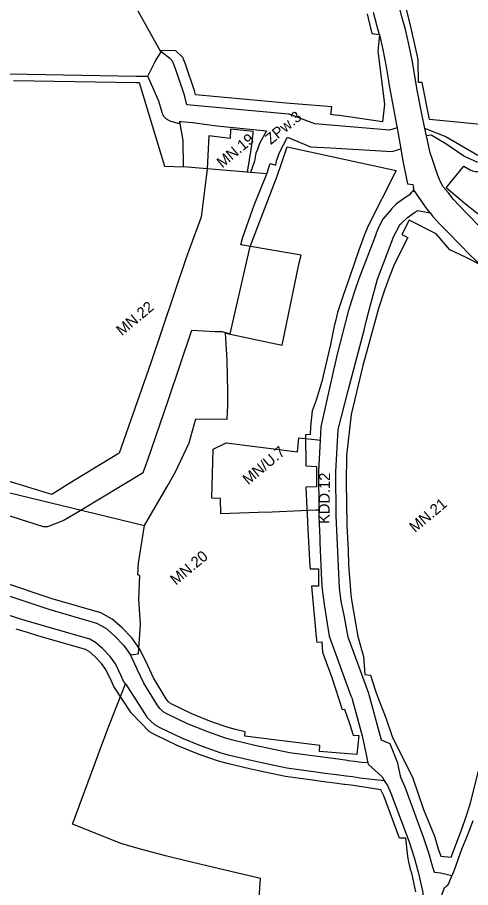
# Model space of a CAD drawing. Extents: x 7418616 to 7420822, y 5550745 to 5553106.
# Drawn here: x 7419932.5 to 7420139.9, y 5552057.3 to 5552455 of the extents above; entities that cross this region are included whole.
import ezdxf

# ---------------------------------------------------------------- set-up
doc = ezdxf.new("R2010")
doc.units = 0
for name, color, linetype in [('linie rozgraniczające', 7, 'Continuous'), ('nieprzekraczalne linie zabudowy', 7, 'Continuous'), ('przeznaczenia terenów', 7, 'Continuous')]:
    doc.layers.add(name, color=color, linetype=linetype)

msp = doc.modelspace()

# ---------------------------------------------------------------- linework, layer by layer
at = {"layer": 'linie rozgraniczające'}
for p, q in [((7420119.69, 5552400.93), (7420118.98, 5552404.25)), ((7420046.7, 5552383.5), (7420039.22, 5552384.12)), ((7420089.21, 5552107.47), (7420100.37, 5552106.25))]:
    msp.add_line(p, q, dxfattribs=at)
for points in [[(7420118.98, 5552404.25), (7420117.7, 5552410.14), (7420115.46, 5552421.78), (7420113.25, 5552434.63), (7420111.63, 5552442.83), (7420110.06, 5552449.46), (7420108.57, 5552454.77), (7420107, 5552460.77)], [(7419998.25, 5552439.19), (7419998.18, 5552439.22), (7419987.78, 5552457.79)], [(7420095.28, 5552457.36), (7420096.79, 5552451.59), (7420098.01, 5552447.24), (7420098.21, 5552447.22), (7420098.16, 5552446.72), (7420098.26, 5552446.35), (7420099.69, 5552440.34), (7420101.24, 5552432.48), (7420102.35, 5552426), (7420102.52, 5552424.72), (7420105.97, 5552405.94), (7420106.22, 5552404.51)], [(7419992.14, 5552428.07), (7419994.56, 5552433.03), (7419995.62, 5552434.82), (7419998.25, 5552439.19)], [(7420106.22, 5552404.51), (7420102.73, 5552403.52), (7420068.67, 5552406.29), (7420056.91, 5552410.74), (7420056.57, 5552410.75), (7420010.03, 5552414.99), (7420009.23, 5552418.27), (7420008.74, 5552419.94), (7420004.72, 5552431.96), (7420003.97, 5552433.91), (7420003.81, 5552434.26), (7420003.62, 5552434.61), (7420003.41, 5552434.94), (7420003.18, 5552435.26), (7420002.94, 5552435.57), (7420002.67, 5552435.85), (7420002.38, 5552436.12), (7420002.08, 5552436.37), (7419998.85, 5552438.79), (7419998.25, 5552439.19)], [(7419926.65, 5552425.28), (7419926.99, 5552429.22), (7419928.76, 5552429.22), (7419986.92, 5552428.2), (7419992.14, 5552428.07)], [(7420006.98, 5552406.44), (7420006.54, 5552406.49), (7420006.04, 5552406.57), (7420005.55, 5552406.69), (7420002.79, 5552407.48), (7420002.16, 5552407.71), (7420001.8, 5552407.87), (7420001.46, 5552408.05), (7420001.12, 5552408.26), (7420000.8, 5552408.49), (7420000.5, 5552408.74), (7420000.21, 5552409.01), (7419999.95, 5552409.29), (7419999.7, 5552409.6), (7419999.47, 5552409.92), (7419999.26, 5552410.25), (7419999.08, 5552410.59), (7419998.91, 5552410.95), (7419998.7, 5552411.55), (7419997.18, 5552416.69), (7419992.14, 5552428.07)], [(7420206.48, 5552414.76), (7420199.14, 5552413.85), (7420162.83, 5552411.03), (7420156.8, 5552405.92), (7420155, 5552397.26), (7420151.77, 5552395.04), (7420146.63, 5552392.74), (7420143.18, 5552391.94), (7420128.29, 5552400.63), (7420118.98, 5552404.25)], [(7420006.98, 5552406.44), (7420006.79, 5552407.54), (7420007.34, 5552407.49), (7420012.61, 5552406.89), (7420020.44, 5552405.83), (7420023.71, 5552405.43), (7420046.41, 5552403.21), (7420043.29, 5552397.35), (7420042.32, 5552394.67), (7420041.6, 5552393), (7420040.96, 5552389.28), (7420039.22, 5552384.12)], [(7420203.99, 5552403.43), (7420199.57, 5552403.26), (7420163.24, 5552408.03), (7420161, 5552407.23), (7420159.6, 5552405.3), (7420157.09, 5552395.64), (7420153.95, 5552392.56), (7420143.19, 5552388.69), (7420136.72, 5552391.55), (7420128.56, 5552397.25), (7420121.84, 5552401.24), (7420119.69, 5552400.93)], [(7420039.22, 5552384.12), (7420008.47, 5552386.68), (7420008.32, 5552398.66), (7420006.98, 5552406.44)], [(7420106.22, 5552404.51), (7420106.69, 5552401.85), (7420107.92, 5552394.9)], [(7420046.7, 5552383.5), (7420048.22, 5552388.16), (7420050.79, 5552387.4), (7420051.1, 5552389.49), (7420052.46, 5552393.32), (7420056.16, 5552400.2), (7420066.62, 5552395.82), (7420075.76, 5552395.35), (7420104, 5552393.77), (7420107.92, 5552394.9)], [(7420147.87, 5552355.44), (7420143.56, 5552359.75), (7420138.73, 5552364.79), (7420134.72, 5552368.9), (7420132.01, 5552371.82), (7420129.55, 5552375.01), (7420127.33, 5552377.61), (7420125.99, 5552380.21), (7420124.9, 5552382.74), (7420123.7, 5552386.34), (7420122.54, 5552389.63), (7420121.39, 5552393.15), (7420119.69, 5552400.93)], [(7420107.92, 5552394.9), (7420108.74, 5552390.22), (7420110.94, 5552378.87), (7420113.43, 5552378.58), (7420113.65, 5552378.01), (7420113.73, 5552376.3)], [(7419990.73, 5552222.78), (7420001.42, 5552241.32), (7420004.84, 5552247.25), (7420011.13, 5552260.48), (7420014.16, 5552271.55), (7420028.46, 5552271.37), (7420028.85, 5552277.74), (7420028.74, 5552284.08), (7420028.48, 5552298.27), (7420027.99, 5552305.76), (7420027.66, 5552310.69), (7420053.64, 5552305.2), (7420061.5, 5552342.83), (7420062.36, 5552346.38), (7420034.68, 5552351), (7420035.59, 5552354.53), (7420040.07, 5552367.09), (7420040.9, 5552369.19), (7420046.7, 5552383.5)], [(7420113.73, 5552376.3), (7420113.36, 5552375.85), (7420113.52, 5552375.4), (7420112.82, 5552375.18), (7420112.18, 5552374.39), (7420112.15, 5552374), (7420109.74, 5552372.46), (7420105.87, 5552369.67), (7420105.67, 5552369.49), (7420103.8, 5552367.62), (7420103.46, 5552367.24), (7420099.78, 5552362.73), (7420097.64, 5552358.67), (7420096.91, 5552356.99), (7420096.69, 5552356.45), (7420096.32, 5552355.38), (7420089.45, 5552337.45), (7420088.75, 5552335.53), (7420086.8, 5552329.69), (7420085.33, 5552325.44), (7420083.82, 5552320.51), (7420078.88, 5552301.03), (7420077.55, 5552295.66), (7420077.45, 5552295.06), (7420071.34, 5552267.92), (7420071.01, 5552261.83)], [(7420121.34, 5552365.68), (7420120.17, 5552367.21), (7420119.7, 5552367.75), (7420118.92, 5552368.85), (7420113.73, 5552376.3)], [(7420131.31, 5552062.66), (7420126.09, 5552063.86), (7420123.32, 5552064.18), (7420122.15, 5552068.09), (7420121.08, 5552072.08), (7420118.37, 5552080.3), (7420109.87, 5552103.21), (7420107.89, 5552107.57), (7420106.84, 5552112.66), (7420106.64, 5552114.1), (7420103, 5552122.97), (7420099.17, 5552124.58), (7420093.38, 5552145.35), (7420093.25, 5552145.94), (7420083.78, 5552171.72), (7420082.06, 5552181.85), (7420080.69, 5552188.08), (7420079.86, 5552194.29), (7420078.81, 5552217.28), (7420078.41, 5552227.23), (7420078.22, 5552247.22), (7420079.29, 5552266.69), (7420083.92, 5552284.52), (7420091.1, 5552312.12), (7420092.2, 5552316.57), (7420094.31, 5552324.72), (7420097.23, 5552335.38), (7420104.76, 5552355.04), (7420106.99, 5552359.25), (7420107.52, 5552360.28), (7420107.93, 5552360.69), (7420110.95, 5552363.47), (7420114.2, 5552365.81), (7420115.57, 5552366.69), (7420121.34, 5552365.68)], [(7420121.34, 5552365.68), (7420122.5, 5552364.16), (7420122.88, 5552363.71), (7420125.85, 5552360.53), (7420129.94, 5552356.33), (7420134.88, 5552351.17), (7420139.67, 5552346.39), (7420144.36, 5552341.98)], [(7420070.39, 5552229.76), (7420069.02, 5552229.7), (7420049.14, 5552228.86), (7420042.7, 5552228.69), (7420025.52, 5552228.07), (7420025.5, 5552235.09), (7420021.5, 5552235.2), (7420022.11, 5552257.69), (7420028.09, 5552260.49), (7420060.74, 5552256.48), (7420061.28, 5552262.81), (7420070.02, 5552261.93), (7420071.01, 5552261.83)], [(7420071.01, 5552261.83), (7420070.22, 5552247.4), (7420070.39, 5552229.76)], [(7419908.48, 5552246.57), (7419908.77, 5552242.61), (7419957.47, 5552230.82), (7419990.73, 5552222.78)], [(7420070.39, 5552229.76), (7420070.41, 5552227.03), (7420070.68, 5552220.3), (7420070.83, 5552216.93), (7420070.9, 5552214.95), (7420071.69, 5552197.66), (7420071.89, 5552193.57), (7420072.8, 5552186.69), (7420075.12, 5552172.11), (7420085.08, 5552144.98), (7420085.47, 5552144.06), (7420085.63, 5552143.37), (7420090.28, 5552126.68), (7420092.4, 5552116.55), (7420092.46, 5552116.54), (7420092.41, 5552116.49), (7420092.88, 5552114.27)], [(7419984.28, 5552163.67), (7419987.97, 5552164.09), (7419988.91, 5552177.68), (7419988.09, 5552189.08), (7419988.52, 5552199.97), (7419987.69, 5552200.14), (7419987.87, 5552205.54), (7419990.73, 5552222.78)], [(7419981.9, 5552150.37), (7419981.07, 5552151.67), (7419979.95, 5552154.09), (7419977.37, 5552159.56), (7419974.89, 5552162.94), (7419971.41, 5552166.55), (7419968.29, 5552169.27), (7419965.64, 5552170.76), (7419943.32, 5552177.2), (7419938.59, 5552178.62), (7419933.5, 5552180.18), (7419928.42, 5552181.83), (7419924.92, 5552182.92), (7419920.1, 5552184.61), (7419899.81, 5552191.79), (7419897.2, 5552192.79), (7419887.17, 5552196.45), (7419873.16, 5552201.3), (7419870.62, 5552202.05)], [(7419902.57, 5552199.3), (7419946.92, 5552184.49), (7419968.76, 5552178.19), (7419972.93, 5552175.83), (7419976.93, 5552172.35), (7419981.02, 5552168.11), (7419984.28, 5552163.67)], [(7420092.88, 5552114.27), (7420089.94, 5552114.44), (7420086.72, 5552114.93), (7420083.9, 5552115.26), (7420083.49, 5552115.33), (7420079.21, 5552115.93), (7420070.98, 5552116.99), (7420057.05, 5552118.9), (7420041.07, 5552122.28), (7420031.13, 5552124.64), (7420027.7, 5552125.52), (7420019.57, 5552128.42), (7420010.35, 5552132.13), (7420000.94, 5552136.67), (7419999.14, 5552137.65), (7419997.67, 5552139.12), (7419996.46, 5552140.82), (7419990.31, 5552150.77), (7419987.34, 5552157.17), (7419984.28, 5552163.67)], [(7420042.7, 5552046.08), (7420043.73, 5552061.39), (7420030.24, 5552064.56), (7420010.13, 5552069.37), (7420000.2, 5552071.75), (7419989.4, 5552074.75), (7419980.25, 5552077.29), (7419957.79, 5552086.22), (7419972.05, 5552124.98), (7419974.6, 5552131.78), (7419981.9, 5552150.37)], [(7419981.9, 5552150.37), (7419982.84, 5552148.95), (7419990.49, 5552137.17), (7419991.81, 5552135.23), (7419993.39, 5552133.43), (7419995.22, 5552131.82), (7419997.74, 5552130.44), (7420007.52, 5552125.72), (7420016.58, 5552122.08), (7420017.09, 5552121.88), (7420025.65, 5552118.82), (7420028.88, 5552117.99), (7420039.54, 5552115.44), (7420043.58, 5552114.6), (7420055.85, 5552112), (7420070.05, 5552110.05), (7420073.22, 5552109.63), (7420078.54, 5552108.96), (7420082.9, 5552108.33), (7420085.79, 5552107.99), (7420089.21, 5552107.47)], [(7420092.88, 5552114.27), (7420093.01, 5552113.63), (7420099.37, 5552107.89), (7420100.37, 5552106.25)], [(7420100.37, 5552106.25), (7420101.77, 5552103.96), (7420103.41, 5552100.49), (7420111.7, 5552078.16), (7420114.08, 5552070.97), (7420114.41, 5552069.91), (7420115.47, 5552066), (7420115.91, 5552064.54), (7420117.99, 5552054.98), (7420117.94, 5552047.13), (7420119.02, 5552046.72), (7420119.61, 5552043.3), (7420122.72, 5552042.44)], [(7420140.84, 5552087.78), (7420138.63, 5552081.71), (7420135.68, 5552074.62), (7420132.32, 5552065.22), (7420131.31, 5552062.66)], [(7420122.72, 5552042.44), (7420127.93, 5552057.32), (7420128.96, 5552057.88), (7420129.49, 5552058.46), (7420129.72, 5552058.64), (7420129.8, 5552058.79), (7420131.31, 5552062.66)]]:
    msp.add_lwpolyline(points, dxfattribs=at)
at = {"layer": 'nieprzekraczalne linie zabudowy'}
for points in [[(7420149.1, 5552405.54), (7420121.07, 5552408.4), (7420117.74, 5552425.21), (7420116.03, 5552425.22), (7420115.81, 5552435.63), (7420115.3, 5552438.48), (7420114.41, 5552442.68), (7420112.21, 5552452.02), (7420110.18, 5552459.81)], [(7420092.55, 5552456.68), (7420093.03, 5552454.59), (7420094.69, 5552447.61), (7420098.21, 5552447.22), (7420097.39, 5552439.63), (7420100.46, 5552415.28), (7420099.61, 5552407.27), (7420078.84, 5552410.32), (7420078.82, 5552410.17), (7420075.98, 5552410.59), (7420076.38, 5552414.09), (7420055.46, 5552415.87), (7420014.04, 5552419.64), (7420013.51, 5552421.44), (7420009.43, 5552433.65), (7420008.57, 5552435.87), (7420008.29, 5552436.48), (7420008.2, 5552436.64), (7420005.06, 5552439.68), (7419997.8, 5552439.89)], [(7419930.74, 5552426.18), (7419986.85, 5552425.21), (7419988.23, 5552425.17), (7419999.85, 5552387.04), (7420008.47, 5552386.68)], [(7420037.72, 5552384.25), (7420039.65, 5552395.5), (7420040.43, 5552401.97), (7420040.33, 5552402.9), (7420029.94, 5552403.87), (7420029.87, 5552399.67), (7420020.16, 5552400.84), (7420019.37, 5552385.79), (7420016.58, 5552363.64), (7420010.89, 5552348.41), (7420009.43, 5552344.19), (7419993.52, 5552297.13), (7419979.08, 5552255.75), (7419955.74, 5552241.59), (7419948.21, 5552236.99), (7419916.24, 5552246.72)], [(7420152.62, 5552357.72), (7420137.53, 5552369.65), (7420128.64, 5552377.15), (7420136.8, 5552386.98), (7420139.71, 5552385.37), (7420140.75, 5552384.9), (7420141.9, 5552384.64), (7420143.07, 5552384.6), (7420144.23, 5552384.79), (7420154.31, 5552387.89), (7420159.58, 5552391.56), (7420157.36, 5552392.49), (7420161.78, 5552400.91), (7420163.11, 5552400.23), (7420164.23, 5552402.73), (7420183.98, 5552402.44), (7420203.73, 5552402.24)], [(7419911.69, 5552232.6), (7419944.34, 5552222.27), (7419946.37, 5552222.32), (7419953.46, 5552225.05), (7419961.2, 5552229.55), (7419990.05, 5552247.01), (7419992.12, 5552252.81), (7420001.49, 5552279.85), (7420012.29, 5552312.1), (7420022.99, 5552311.4), (7420026.13, 5552311.36), (7420029.91, 5552310.33), (7420039.05, 5552350.27), (7420051.42, 5552382.5), (7420055.99, 5552395.86), (7420105.84, 5552385), (7420092.87, 5552359.39), (7420091.23, 5552355.33), (7420088.75, 5552348.67), (7420084.69, 5552337), (7420081.62, 5552327.89), (7420079.12, 5552320.61), (7420078.97, 5552320.13), (7420077.83, 5552315.55), (7420077.6, 5552314.69), (7420075.73, 5552305.44), (7420071.74, 5552288.56), (7420069.26, 5552280.01), (7420067.36, 5552275.16), (7420066.65, 5552267.82), (7420066.45, 5552264.42), (7420064.25, 5552264.27), (7420064.55, 5552250.01), (7420069.31, 5552249.71), (7420069.29, 5552240.4), (7420064.53, 5552240.28), (7420064.88, 5552230.59), (7420065.2, 5552224.82), (7420065.18, 5552224.3), (7420065.19, 5552223.94), (7420066.38, 5552204.03), (7420066.47, 5552202.99), (7420070.34, 5552202.93), (7420070.23, 5552194.97), (7420067.14, 5552195.03), (7420069.14, 5552171.7), (7420069.45, 5552169.39), (7420071.75, 5552169.64), (7420072.17, 5552164.88), (7420074.36, 5552158.55), (7420074.69, 5552157.88), (7420076.42, 5552153.31), (7420081.17, 5552138.73), (7420082.11, 5552138.77), (7420084.38, 5552132.34), (7420086.18, 5552126.97), (7420088.71, 5552126.79), (7420087.86, 5552118.03), (7420070.79, 5552119.45), (7420070.93, 5552122.2), (7420036.53, 5552126.51), (7420036.75, 5552128.44), (7420032.25, 5552129.51), (7420028.95, 5552130.38), (7420021.34, 5552133.1), (7420012.37, 5552136.71), (7420003.22, 5552141.12), (7420002.16, 5552141.7), (7420001.5, 5552142.36), (7420000.63, 5552143.59), (7419994.72, 5552153.15), (7419992.14, 5552158.72), (7419988.6, 5552166.24), (7419984.83, 5552171.36), (7419980.38, 5552175.98), (7419975.83, 5552179.94), (7419970.71, 5552182.83), (7419948.41, 5552189.26), (7419904.25, 5552204.01)], [(7420146.26, 5552341.05), (7420137.49, 5552345.36), (7420130.35, 5552348.73), (7420124.16, 5552356.1), (7420111.75, 5552362.34), (7420108.38, 5552355.82), (7420111.17, 5552354.42), (7420104.83, 5552341.99), (7420102.67, 5552336.13), (7420100.5, 5552330.38), (7420097.66, 5552321.92), (7420092.38, 5552302.47), (7420090.62, 5552295.92), (7420089.14, 5552290.04), (7420085.28, 5552273.54), (7420083.15, 5552254.69), (7420082.92, 5552242.19)], [(7420082.92, 5552242.19), (7420083.02, 5552233.35), (7420083.17, 5552222.78), (7420083.77, 5552211.43), (7420083.93, 5552204.97), (7420085.04, 5552191.2), (7420085.36, 5552188.76), (7420087.01, 5552178.98), (7420088.21, 5552172.06), (7420090.84, 5552162.88), (7420091.46, 5552154.68), (7420094.06, 5552154.37), (7420096.32, 5552147.2), (7420097.24, 5552144.68), (7420101.06, 5552134.93), (7420104.05, 5552126.34), (7420113.44, 5552107.31), (7420118.36, 5552092.9), (7420123.3, 5552080.72), (7420123.42, 5552080.35), (7420124.83, 5552075.51), (7420126.24, 5552071.58), (7420130.93, 5552071.2), (7420135.97, 5552084.46), (7420137.73, 5552089.35), (7420139.59, 5552095.33), (7420143.45, 5552110.54)], [(7420114.85, 5552055.26), (7420113, 5552063.79), (7420112.59, 5552065.14), (7420111.53, 5552069.07), (7420111.21, 5552071.48), (7420110.17, 5552079.85), (7420107.36, 5552079.79), (7420100.18, 5552099.13), (7420098.83, 5552101.99), (7420085.26, 5552104.02), (7420082.33, 5552104.37), (7420081.8, 5552104.46), (7420077.76, 5552105.02), (7420072.69, 5552105.67), (7420067.48, 5552106.36), (7420055.16, 5552108.06), (7420042.76, 5552110.69), (7420038.67, 5552111.54), (7420028.51, 5552113.96), (7420024.48, 5552114.99), (7420015.67, 5552118.13), (7420005.9, 5552122.06), (7419995.91, 5552126.88), (7419992.91, 5552128.52), (7419984.52, 5552137.18), (7419976.69, 5552149.24), (7419975.42, 5552151.98), (7419973.05, 5552156.99), (7419971.06, 5552159.7), (7419967.96, 5552162.92), (7419965.38, 5552165.17), (7419963.69, 5552166.12), (7419941.93, 5552172.4), (7419937.16, 5552173.83), (7419932.03, 5552175.4)]]:
    msp.add_lwpolyline(points, dxfattribs=at)

# ---------------------------------------------------------------- texts
at = {"layer": 'przeznaczenia terenów'}
for s, rotation, p in [('ZPw.3', 39.8439, (7420048.47, 5552396.62)), ('MN.19', 39.8439, (7420026.27, 5552385.91)), ('MN.22', 39.8439, (7419980.31, 5552309.24)), ('MN/U.7', 39.8439, (7420038.12, 5552241.08)), ('KDD.12', 89.1846, (7420075.26, 5552223.47)), ('MN.21', 39.8439, (7420114.43, 5552219.28)), ('MN.20', 39.8439, (7420005.03, 5552195.27))]:
    msp.add_text(s, height=5, rotation=rotation, dxfattribs=at).set_placement(p)

doc.saveas('drawing.dxf')
